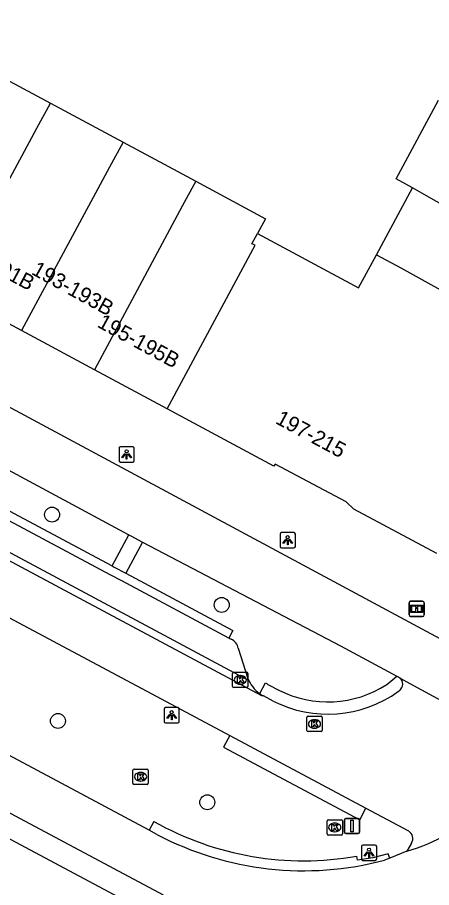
# Model space of a CAD drawing. Extents: x 159489 to 160304, y 383826 to 384530.
# Drawn here: x 159768.9 to 159796, y 384002.8 to 384059.8 of the extents above; entities that cross this region are included whole.
import ezdxf

# ---------------------------------------------------------------- set-up
doc = ezdxf.new("R2010")
doc.units = 0
for name, color, linetype in [('IMGEO_Berm_open', 7, 'Continuous'), ('IMGEO_Boom', 7, 'Continuous'), ('IMGEO_Fietspad_gesloten', 7, 'Continuous'), ('IMGEO_Informatiebord', 7, 'Continuous'), ('IMGEO_Kolk', 7, 'Continuous'), ('IMGEO_Lichtpunt', 7, 'Continuous'), ('IMGEO_OVBaan_gesloten', 7, 'Continuous'), ('IMGEO_Pand', 7, 'Continuous'), ('IMGEO_Pand_nummerreeks', 7, 'Continuous'), ('IMGEO_Parkeervlak_open', 7, 'Continuous'), ('IMGEO_Rijbaan_lokaal_gesloten', 7, 'Continuous'), ('IMGEO_Rijbaan_lokaal_open', 7, 'Continuous'), ('IMGEO_Verkeersbordpaal', 7, 'Continuous'), ('IMGEO_Voetpad_open', 7, 'Continuous')]:
    doc.layers.add(name, color=color, linetype=linetype)

msp = doc.modelspace()

# ---------------------------------------------------------------- linework, layer by layer
at = {"layer": 'IMGEO_Berm_open'}
for points in [[(159793.026, 384016.123), (159793.68, 384016.677)], [(159784.719, 384015.525), (159785.101, 384016.235), (159785.176, 384016.179), (159785.254, 384016.128), (159785.335, 384016.083), (159785.966, 384015.746)], [(159782.754, 384012.782), (159782.348, 384012.022), (159791.261, 384007.258), (159791.668, 384008.018)], [(159777.79, 384007.155), (159777.482, 384006.579)], [(159793.224, 384004.76), (159793.112, 384005.034), (159792.127, 384004.778), (159791.106, 384004.627), (159791.06, 384004.885)]]:
    msp.add_lwpolyline(points, dxfattribs=at)
for centre, radius, start, end in [((159789.168, 384022.07), 7.089, 243.1444, 302.9689), ((159787.583, 384024.482), 19.903, 240.5246, 280.061)]:
    msp.add_arc(centre, radius, start, end, dxfattribs=at)
at = {"layer": 'IMGEO_Boom'}
for centre in [(159771.136, 384027.249), (159782.231, 384021.336), (159771.522, 384013.734), (159781.289, 384008.412)]:
    msp.add_circle(centre, 0.489, dxfattribs=at)
at = {"layer": 'IMGEO_Fietspad_gesloten'}
for points in [[(159797.098, 384018.803), (159731.166, 384054.292)], [(159766.543, 384031.098), (159776.103, 384025.957), (159776.158, 384025.928)], [(159776.158, 384025.928), (159776.288, 384025.857), (159777.06, 384025.441)], [(159777.06, 384025.441), (159789.993, 384018.658), (159793.68, 384016.677)], [(159793.68, 384016.677), (159793.765, 384016.631), (159793.788, 384016.619), (159793.901, 384016.538)]]:
    msp.add_lwpolyline(points, dxfattribs=at)
at = {"layer": 'IMGEO_Informatiebord'}
for p, q in [((159794.485, 384020.677), (159794.485, 384021.477)), ((159794.485, 384021.477), (159794.485, 384020.677)), ((159794.585, 384021.577), (159795.375, 384021.577)), ((159795.375, 384021.577), (159794.585, 384021.577)), ((159795.475, 384021.477), (159795.475, 384020.677)), ((159795.475, 384020.677), (159795.475, 384021.477)), ((159795.375, 384020.577), (159794.585, 384020.577)), ((159794.585, 384020.577), (159795.375, 384020.577))]:
    msp.add_line(p, q, dxfattribs=at)
for points in [[(159794.586, 384021.309), (159795.374, 384021.309), (159795.374, 384020.845), (159794.586, 384020.845), (159794.586, 384021.309)], [(159794.651, 384021.244), (159794.651, 384020.91), (159794.926, 384020.91), (159794.927, 384021.123), (159795.031, 384021.124), (159795.032, 384020.91), (159795.309, 384020.91), (159795.309, 384021.244), (159795.033, 384021.244), (159795.033, 384021.164), (159794.927, 384021.164), (159794.927, 384021.244), (159794.651, 384021.244)]]:
    msp.add_lwpolyline(points, dxfattribs=at)
for centre, start, end in [((159794.585, 384021.477), 90, 180), ((159794.585, 384021.477), 90, 180), ((159795.375, 384021.477), 0, 90), ((159795.375, 384021.477), 360, 90), ((159794.585, 384020.677), 180, 270), ((159794.585, 384020.677), 180, 270), ((159795.375, 384020.677), 270, 0), ((159795.375, 384020.677), 270, 0)]:
    msp.add_arc(centre, 0.1, start, end, dxfattribs=at)
at = {"layer": 'IMGEO_Kolk'}
for p, q in [((159782.946, 384015.998), (159782.946, 384016.85)), ((159783.021, 384016.924), (159783.873, 384016.924)), ((159783.947, 384016.85), (159783.947, 384015.998)), ((159783.434, 384016.704), (159783.459, 384016.704)), ((159783.873, 384015.924), (159783.021, 384015.924)), ((159783.457, 384016.144), (159783.432, 384016.144)), ((159787.876, 384014.04), (159788.728, 384014.04)), ((159787.801, 384013.114), (159787.801, 384013.966)), ((159788.289, 384013.82), (159788.314, 384013.82)), ((159788.802, 384013.966), (159788.802, 384013.114)), ((159788.728, 384013.04), (159787.876, 384013.04)), ((159788.312, 384013.26), (159788.287, 384013.26)), ((159776.501, 384010.58), (159777.353, 384010.58)), ((159776.426, 384009.654), (159776.426, 384010.506)), ((159776.914, 384010.36), (159776.939, 384010.36)), ((159777.427, 384010.506), (159777.427, 384009.654)), ((159777.353, 384009.58), (159776.501, 384009.58)), ((159776.937, 384009.8), (159776.912, 384009.8)), ((159789.124, 384006.338), (159789.124, 384007.19)), ((159789.199, 384007.264), (159790.051, 384007.264)), ((159790.125, 384007.19), (159790.125, 384006.338)), ((159789.612, 384007.044), (159789.637, 384007.044)), ((159790.051, 384006.264), (159789.199, 384006.264)), ((159789.635, 384006.484), (159789.61, 384006.484))]:
    msp.add_line(p, q, dxfattribs=at)
for points in [[(159782.946, 384015.998), (159782.946, 384016.85)], [(159783.021, 384016.924), (159783.873, 384016.924)], [(159783.947, 384016.85), (159783.947, 384015.998)], [(159783.267, 384016.624), (159783.39, 384016.624), (159783.39, 384016.473), (159783.52, 384016.624), (159783.684, 384016.624), (159783.538, 384016.473), (159783.691, 384016.224), (159783.539, 384016.224), (159783.454, 384016.388), (159783.39, 384016.321), (159783.39, 384016.224), (159783.267, 384016.224), (159783.267, 384016.624)], [(159783.873, 384015.924), (159783.021, 384015.924)], [(159787.876, 384014.04), (159788.728, 384014.04)], [(159787.801, 384013.114), (159787.801, 384013.966)], [(159788.122, 384013.74), (159788.245, 384013.74), (159788.245, 384013.589), (159788.375, 384013.74), (159788.539, 384013.74), (159788.393, 384013.589), (159788.546, 384013.34), (159788.394, 384013.34), (159788.309, 384013.504), (159788.245, 384013.437), (159788.245, 384013.34), (159788.122, 384013.34), (159788.122, 384013.74)], [(159788.802, 384013.966), (159788.802, 384013.114)], [(159788.728, 384013.04), (159787.876, 384013.04)], [(159776.501, 384010.58), (159777.353, 384010.58)], [(159776.426, 384009.654), (159776.426, 384010.506)], [(159776.747, 384010.28), (159776.87, 384010.28), (159776.87, 384010.129), (159777, 384010.28), (159777.164, 384010.28), (159777.018, 384010.129), (159777.171, 384009.88), (159777.019, 384009.88), (159776.934, 384010.044), (159776.87, 384009.977), (159776.87, 384009.88), (159776.747, 384009.88), (159776.747, 384010.28)], [(159777.427, 384010.506), (159777.427, 384009.654)], [(159777.353, 384009.58), (159776.501, 384009.58)], [(159789.124, 384006.338), (159789.124, 384007.19)], [(159789.199, 384007.264), (159790.051, 384007.264)], [(159790.125, 384007.19), (159790.125, 384006.338)], [(159789.445, 384006.964), (159789.568, 384006.964), (159789.568, 384006.813), (159789.698, 384006.964), (159789.862, 384006.964), (159789.716, 384006.813), (159789.869, 384006.564), (159789.717, 384006.564), (159789.632, 384006.728), (159789.568, 384006.661), (159789.568, 384006.564), (159789.445, 384006.564), (159789.445, 384006.964)], [(159790.051, 384006.264), (159789.199, 384006.264)]]:
    msp.add_lwpolyline(points, dxfattribs=at)
for centre, start, end in [((159783.023, 384016.848), 91.552, 178.448), ((159783.023, 384016.848), 91.552, 178.448), ((159783.871, 384016.848), 1.552, 88.448), ((159783.871, 384016.848), 1.552, 88.448), ((159783.023, 384016), 181.552, 268.448), ((159783.023, 384016), 181.552, 268.448), ((159783.871, 384016), 271.552, 358.448), ((159783.871, 384016), 271.552, 358.448), ((159787.878, 384013.964), 91.552, 178.448), ((159787.878, 384013.964), 91.552, 178.448), ((159788.726, 384013.964), 1.552, 88.448), ((159788.726, 384013.964), 1.552, 88.448), ((159787.878, 384013.116), 181.552, 268.448), ((159787.878, 384013.116), 181.552, 268.448), ((159788.726, 384013.116), 271.552, 358.448), ((159788.726, 384013.116), 271.552, 358.448), ((159776.503, 384010.504), 91.552, 178.448), ((159776.503, 384010.504), 91.552, 178.448), ((159777.351, 384010.504), 1.552, 88.448), ((159777.351, 384010.504), 1.552, 88.448), ((159776.503, 384009.656), 181.552, 268.448), ((159776.503, 384009.656), 181.552, 268.448), ((159777.351, 384009.656), 271.552, 358.448), ((159777.351, 384009.656), 271.552, 358.448), ((159789.201, 384007.188), 91.552, 178.448), ((159789.201, 384007.188), 91.552, 178.448), ((159790.049, 384007.188), 1.552, 88.448), ((159790.049, 384007.188), 1.552, 88.448), ((159789.201, 384006.34), 181.552, 268.448), ((159789.201, 384006.34), 181.552, 268.448), ((159790.049, 384006.34), 271.552, 358.448), ((159790.049, 384006.34), 271.552, 358.448)]:
    msp.add_arc(centre, 0.0765, start, end, dxfattribs=at)
for centre, major_axis, ratio, start_param, end_param in [((159783.433, 384016.424), (-0.387, 0.002), 0.722429, 4.712389, 7.853982), ((159783.458, 384016.424), (-0.39, 0.002), 0.717154, 1.570796, 4.712389), ((159788.288, 384013.54), (-0.387, 0.002), 0.722429, 4.712389, 7.853982), ((159788.313, 384013.54), (-0.39, 0.002), 0.717154, 1.570796, 4.712389), ((159776.913, 384010.08), (-0.387, 0.002), 0.722429, 4.712389, 7.853982), ((159776.938, 384010.08), (-0.39, 0.002), 0.717154, 1.570796, 4.712389), ((159789.611, 384006.764), (-0.387, 0.002), 0.722429, 4.712389, 7.853982), ((159789.636, 384006.764), (-0.39, 0.002), 0.717154, 1.570796, 4.712389)]:
    msp.add_ellipse(centre, major_axis=major_axis, ratio=ratio, start_param=start_param, end_param=end_param, dxfattribs=at)
at = {"layer": 'IMGEO_Lichtpunt'}
for p, q in [((159776.415, 384031.689), (159775.607, 384031.689)), ((159776.415, 384031.689), (159775.607, 384031.689)), ((159775.513, 384031.594), (159775.513, 384030.787)), ((159775.513, 384031.594), (159775.513, 384030.787)), ((159776.509, 384030.787), (159776.509, 384031.594)), ((159776.509, 384030.787), (159776.509, 384031.594)), ((159775.607, 384030.693), (159776.415, 384030.693)), ((159775.607, 384030.693), (159776.415, 384030.693)), ((159786.051, 384025.974), (159786.051, 384025.167)), ((159786.051, 384025.974), (159786.051, 384025.167)), ((159786.953, 384026.069), (159786.145, 384026.069)), ((159786.953, 384026.069), (159786.145, 384026.069)), ((159787.047, 384025.167), (159787.047, 384025.974)), ((159787.047, 384025.167), (159787.047, 384025.974)), ((159786.145, 384025.073), (159786.953, 384025.073)), ((159786.145, 384025.073), (159786.953, 384025.073)), ((159779.364, 384014.608), (159778.556, 384014.608)), ((159779.364, 384014.608), (159778.556, 384014.608)), ((159778.462, 384014.513), (159778.462, 384013.706)), ((159778.462, 384014.513), (159778.462, 384013.706)), ((159779.458, 384013.706), (159779.458, 384014.513)), ((159779.458, 384013.706), (159779.458, 384014.513)), ((159778.556, 384013.612), (159779.364, 384013.612)), ((159778.556, 384013.612), (159779.364, 384013.612)), ((159791.371, 384005.508), (159791.371, 384004.701)), ((159791.371, 384005.508), (159791.371, 384004.701)), ((159792.273, 384005.603), (159791.465, 384005.603)), ((159792.273, 384005.603), (159791.465, 384005.603)), ((159792.367, 384004.701), (159792.367, 384005.508)), ((159792.367, 384004.701), (159792.367, 384005.508)), ((159791.465, 384004.607), (159792.273, 384004.607)), ((159791.465, 384004.607), (159792.273, 384004.607))]:
    msp.add_line(p, q, dxfattribs=at)
for points in [[(159775.887, 384031.258), (159775.926, 384031.23), (159775.738, 384030.968), (159775.7, 384030.995), (159775.887, 384031.258)], [(159775.989, 384031.21), (159776.036, 384031.21), (159776.036, 384030.888), (159775.989, 384030.888), (159775.989, 384031.21)], [(159776.099, 384031.23), (159776.137, 384031.257), (159776.324, 384030.995), (159776.285, 384030.967), (159776.099, 384031.23)], [(159786.425, 384025.638), (159786.464, 384025.61), (159786.276, 384025.348), (159786.238, 384025.375), (159786.425, 384025.638)], [(159786.527, 384025.59), (159786.574, 384025.59), (159786.574, 384025.268), (159786.527, 384025.268), (159786.527, 384025.59)], [(159786.637, 384025.61), (159786.675, 384025.637), (159786.862, 384025.375), (159786.823, 384025.347), (159786.637, 384025.61)], [(159778.836, 384014.177), (159778.875, 384014.149), (159778.687, 384013.887), (159778.649, 384013.914), (159778.836, 384014.177)], [(159778.938, 384014.129), (159778.985, 384014.129), (159778.985, 384013.807), (159778.938, 384013.807), (159778.938, 384014.129)], [(159779.048, 384014.149), (159779.086, 384014.176), (159779.273, 384013.914), (159779.234, 384013.886), (159779.048, 384014.149)], [(159791.745, 384005.172), (159791.784, 384005.144), (159791.596, 384004.882), (159791.558, 384004.909), (159791.745, 384005.172)], [(159791.847, 384005.124), (159791.894, 384005.124), (159791.894, 384004.802), (159791.847, 384004.802), (159791.847, 384005.124)], [(159791.957, 384005.144), (159791.995, 384005.171), (159792.182, 384004.909), (159792.143, 384004.881), (159791.957, 384005.144)]]:
    msp.add_lwpolyline(points, dxfattribs=at)
for centre in [(159776.012, 384031.392), (159786.55, 384025.772), (159778.961, 384014.311), (159791.87, 384005.306)]:
    msp.add_circle(centre, 0.0994, dxfattribs=at)
for centre, start, end in [((159775.607, 384031.594), 90, 180), ((159775.607, 384031.594), 90, 180), ((159776.415, 384031.594), 0, 90), ((159776.415, 384031.594), 0, 90), ((159775.607, 384030.787), 180, 270), ((159775.607, 384030.787), 180, 270), ((159776.415, 384030.787), 270, 0), ((159776.415, 384030.787), 270, 360), ((159786.145, 384025.974), 90, 180), ((159786.145, 384025.974), 90, 180), ((159786.953, 384025.974), 0, 90), ((159786.953, 384025.974), 0, 90), ((159786.145, 384025.167), 180, 270), ((159786.145, 384025.167), 180, 270), ((159786.953, 384025.167), 270, 0), ((159786.953, 384025.167), 270, 360), ((159778.556, 384014.513), 90, 180), ((159778.556, 384014.513), 90, 180), ((159779.364, 384014.513), 0, 90), ((159779.364, 384014.513), 0, 90), ((159778.556, 384013.706), 180, 270), ((159778.556, 384013.706), 180, 270), ((159779.364, 384013.706), 270, 0), ((159779.364, 384013.706), 270, 360), ((159791.465, 384005.508), 90, 180), ((159791.465, 384005.508), 90, 180), ((159792.273, 384005.508), 0, 90), ((159792.273, 384005.508), 0, 90), ((159791.465, 384004.701), 180, 270), ((159791.465, 384004.701), 180, 270), ((159792.273, 384004.701), 270, 0), ((159792.273, 384004.701), 270, 360)]:
    msp.add_arc(centre, 0.0946, start, end, dxfattribs=at)
at = {"layer": 'IMGEO_OVBaan_gesloten'}
for points in [[(159778.419, 384002.326), (159655.116, 384068.233), (159654.047, 384068.903), (159653.178, 384069.297)], [(159777.482, 384006.579), (159693.976, 384051.25)], [(159777.995, 384006.304), (159777.482, 384006.579)], [(159794.349, 384005.218), (159793.224, 384004.76)], [(159793.224, 384004.76), (159792.881, 384004.62)]]:
    msp.add_lwpolyline(points, dxfattribs=at)
for centre, radius, start, end in [((159791.43, 384015.836), 11.012, 285.3708, 315.3707), ((159787.586, 384024.445), 20.52, 242.1367, 284.9549)]:
    msp.add_arc(centre, radius, start, end, dxfattribs=at)
at = {"layer": 'IMGEO_Pand'}
for points in [[(159766.267, 384056.759), (159771.029, 384054.198)], [(159764.388, 384041.852), (159770.147, 384052.559), (159771.029, 384054.198)], [(159771.029, 384054.198), (159775.785, 384051.64)], [(159794.711, 384048.642), (159793.646, 384049.235), (159796.419, 384054.39)], [(159775.785, 384051.64), (159774.902, 384050.001), (159769.137, 384039.299)], [(159775.785, 384051.64), (159780.536, 384049.085)], [(159780.536, 384049.085), (159779.655, 384047.445), (159773.904, 384036.736)], [(159780.536, 384049.085), (159785.098, 384046.631), (159784.572, 384045.652)], [(159792.356, 384044.263), (159794.711, 384048.642)], [(159804.812, 384043.02), (159796.285, 384047.766), (159795.323, 384048.301), (159794.711, 384048.642)], [(159778.666, 384034.176), (159784.42, 384044.886), (159784.211, 384044.994), (159784.572, 384045.652)], [(159784.572, 384045.652), (159791.189, 384042.093), (159792.356, 384044.263)], [(159792.356, 384044.263), (159793.941, 384043.41), (159802.47, 384038.666)], [(159769.137, 384039.299), (159764.388, 384041.852)], [(159773.904, 384036.736), (159769.137, 384039.299)], [(159778.666, 384034.176), (159773.904, 384036.736)], [(159796.313, 384024.693), (159790.874, 384027.608), (159790.367, 384028.077), (159785.732, 384030.559), (159785.645, 384030.424), (159778.666, 384034.176)]]:
    msp.add_lwpolyline(points, dxfattribs=at)
at = {"layer": 'IMGEO_Parkeervlak_open'}
for points in [[(159782.699, 384019.159), (159782.841, 384019.083)], [(159783.314, 384018.492), (159783.95, 384016.527)]]:
    msp.add_lwpolyline(points, dxfattribs=at)
msp.add_arc((159782.548, 384018.364), 0.777, 9.5048, 67.8384, dxfattribs=at)
at = {"layer": 'IMGEO_Rijbaan_lokaal_gesloten'}
for points in [[(159651.039, 384068.82), (159654.602, 384066.798), (159694.996, 384045.215), (159777.713, 384001.02)], [(159722.71, 384044.871), (159782.754, 384012.782)], [(159784.967, 384015.376), (159784.85, 384015.386), (159732.397, 384043.459), (159732.479, 384043.633)], [(159793.901, 384016.538), (159793.974, 384016.452)], [(159793.901, 384016.538), (159794.526, 384016.198), (159800.871, 384012.75)], [(159785.598, 384015.039), (159784.967, 384015.376)], [(159782.754, 384012.782), (159791.668, 384008.018)], [(159791.668, 384008.018), (159794.454, 384006.529)], [(159794.65, 384005.731), (159794.349, 384005.218)]]:
    msp.add_lwpolyline(points, dxfattribs=at)
for centre, radius, start, end in [((159793.533, 384016.149), 0.535, 298.2123, 34.5168), ((159789.169, 384022.064), 7.881, 243.0529, 305.858), ((159794.145, 384006.03), 0.587, 329.3594, 58.2396)]:
    msp.add_arc(centre, radius, start, end, dxfattribs=at)
at = {"layer": 'IMGEO_Rijbaan_lokaal_open'}
msp.add_lwpolyline([(159732.479, 384043.633), (159733.023, 384043.708), (159783.959, 384016.413), (159783.95, 384016.527)], dxfattribs=at)
for centre, radius, start, end in [((159785.919, 384017.242), 2.095, 199.9562, 235.0537), ((159785.839, 384017.108), 1.939, 234.7248, 243.2798)]:
    msp.add_arc(centre, radius, start, end, dxfattribs=at)
at = {"layer": 'IMGEO_Verkeersbordpaal'}
for p, q in [((159790.256, 384006.458), (159790.256, 384007.258)), ((159790.256, 384007.258), (159790.256, 384006.458)), ((159790.356, 384007.358), (159791.146, 384007.358)), ((159791.146, 384007.358), (159790.356, 384007.358)), ((159791.246, 384007.258), (159791.246, 384006.458)), ((159791.246, 384006.458), (159791.246, 384007.258)), ((159791.146, 384006.358), (159790.356, 384006.358)), ((159790.356, 384006.358), (159791.146, 384006.358))]:
    msp.add_line(p, q, dxfattribs=at)
msp.add_lwpolyline([(159790.676, 384007.233), (159790.826, 384007.233), (159790.826, 384006.483), (159790.676, 384006.483), (159790.676, 384007.233)], dxfattribs=at)
for centre, start, end in [((159790.356, 384007.258), 90, 180), ((159790.356, 384007.258), 90, 180), ((159791.146, 384007.258), 0, 90), ((159791.146, 384007.258), 360, 90), ((159790.356, 384006.458), 180, 270), ((159790.356, 384006.458), 180, 270), ((159791.146, 384006.458), 270, 0), ((159791.146, 384006.458), 270, 0)]:
    msp.add_arc(centre, 0.1, start, end, dxfattribs=at)
at = {"layer": 'IMGEO_Voetpad_open'}
for points in [[(159782.699, 384019.159), (159775.691, 384022.903), (159774.939, 384023.305), (159765.175, 384028.522), (159764.408, 384028.932), (159754.714, 384034.111), (159753.949, 384034.52), (159744.117, 384039.773), (159743.356, 384040.18), (159735.862, 384044.184)], [(159765.444, 384029.028), (159775.012, 384023.915), (159775.067, 384023.886)], [(159775.067, 384023.886), (159776.158, 384025.928)], [(159777.06, 384025.441), (159775.963, 384023.407)], [(159775.067, 384023.886), (159775.207, 384023.811), (159775.963, 384023.407)], [(159775.963, 384023.407), (159782.969, 384019.664), (159782.699, 384019.159)]]:
    msp.add_lwpolyline(points, dxfattribs=at)

# ---------------------------------------------------------------- texts
at = {"layer": 'IMGEO_Pand_nummerreeks'}
for s, rotation, p in [('191-191B', 331.7818, (159764.533, 384044.627)), ('193-193B', 331.0885, (159769.73, 384043.027)), ('195-195B', 331.4266, (159774.026, 384039.574)), ('197-215', 331.607, (159785.68, 384033.261))]:
    msp.add_text(s, height=1, rotation=rotation, dxfattribs=at).set_placement(p)

doc.saveas('drawing.dxf')
